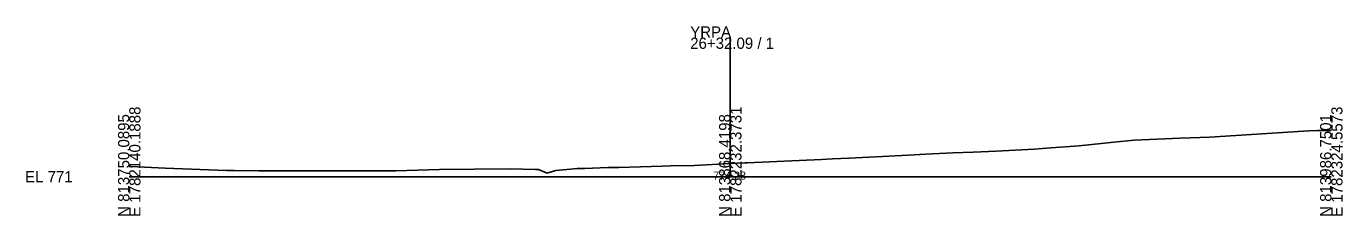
# Model space of a CAD drawing. Extents: x -26 to 2603, y -14 to 9545.
# Drawn here: x 2274.3 to 2602.8, y 3490.3 to 3537.5 of the extents above; entities that cross this region are included whole.
import ezdxf

# ---------------------------------------------------------------- set-up
doc = ezdxf.new("R2010")
doc.units = 0
for name, color, linetype in [('Exist Cross Section Cell', 7, 'Continuous'), ('Exist XS Center Line Elevation Label', 7, 'Continuous'), ('Exist XS Ground Line', 7, 'Continuous')]:
    doc.layers.add(name, color=color, linetype=linetype)

msp = doc.modelspace()

# ---------------------------------------------------------------- linework, layer by layer
at = {"layer": 'Exist Cross Section Cell'}
for p, q in [((2450, 3500), (2450, 3534.67)), ((2300, 3500), (2450, 3500)), ((2450, 3500), (2600, 3500))]:
    msp.add_line(p, q, dxfattribs=at)
at = {"layer": 'Exist XS Ground Line'}
for p, q in [((2545.71, 3508.61), (2550.78, 3509.12)), ((2550.78, 3509.12), (2562.32, 3509.64)), ((2562.32, 3509.64), (2569.71, 3509.9)), ((2569.71, 3509.9), (2593.1, 3511.32)), ((2593.1, 3511.32), (2594.45, 3511.4)), ((2594.45, 3511.4), (2596.62, 3511.52)), ((2596.62, 3511.52), (2597.5, 3511.53)), ((2597.5, 3511.53), (2600, 3511.56)), ((2494.37, 3505.38), (2498.84, 3505.63)), ((2498.84, 3505.63), (2505.53, 3505.93)), ((2505.53, 3505.93), (2510.65, 3506.15)), ((2510.65, 3506.15), (2516.37, 3506.39)), ((2516.37, 3506.39), (2525.81, 3506.83)), ((2525.81, 3506.83), (2529.97, 3507.19)), ((2529.97, 3507.19), (2537.04, 3507.71)), ((2537.04, 3507.71), (2545.71, 3508.61)), ((2300, 3502.56), (2300.36, 3502.55)), ((2300.36, 3502.55), (2308.93, 3502.1)), ((2413.71, 3502.08), (2419.42, 3502.29)), ((2419.42, 3502.29), (2422.16, 3502.33)), ((2422.16, 3502.33), (2432.99, 3502.64)), ((2432.99, 3502.64), (2435.08, 3502.69)), ((2435.08, 3502.69), (2441.06, 3502.84)), ((2441.06, 3502.84), (2450, 3503.28)), ((2450, 3503.28), (2453.6, 3503.46)), ((2453.6, 3503.46), (2454.22, 3503.49)), ((2454.22, 3503.49), (2472.73, 3504.31)), ((2472.73, 3504.31), (2475.52, 3504.45)), ((2475.52, 3504.45), (2479.68, 3504.63)), ((2479.68, 3504.63), (2487.96, 3505.03)), ((2487.96, 3505.03), (2494.37, 3505.38)), ((2308.93, 3502.1), (2324.25, 3501.58)), ((2324.25, 3501.58), (2325.11, 3501.56)), ((2325.11, 3501.56), (2325.74, 3501.56)), ((2325.74, 3501.56), (2326.21, 3501.55)), ((2326.21, 3501.55), (2332.36, 3501.5)), ((2332.36, 3501.5), (2341.54, 3501.46)), ((2341.54, 3501.46), (2342.44, 3501.44)), ((2342.44, 3501.44), (2343.86, 3501.44)), ((2343.86, 3501.44), (2366.52, 3501.51)), ((2366.52, 3501.51), (2377.45, 3501.77)), ((2377.45, 3501.77), (2386.11, 3501.92)), ((2386.11, 3501.92), (2395.28, 3501.99)), ((2395.28, 3501.99), (2401.35, 3501.79)), ((2401.35, 3501.79), (2402.13, 3501.77)), ((2402.13, 3501.77), (2404.33, 3500.91)), ((2404.33, 3500.91), (2406.1, 3501.5)), ((2406.1, 3501.5), (2406.47, 3501.56)), ((2406.47, 3501.56), (2410.15, 3501.87)), ((2410.15, 3501.87), (2411.8, 3502.05)), ((2411.8, 3502.05), (2413.71, 3502.08))]:
    msp.add_line(p, q, dxfattribs=at)

# ---------------------------------------------------------------- texts
at = {"layer": 'Exist Cross Section Cell'}
for s, p in [('YRPA', (2440, 3534.67)), ('26+32.09 / 1', (2440, 3531.87)), ('EL 771', (2274, 3498.6))]:
    msp.add_text(s, height=2.8, dxfattribs=at).set_placement(p)
for s, p in [('N 813750.0895', (2300, 3490)), ('E 1782140.1888', (2302.8, 3490)), ('N 813868.4198', (2450, 3490)), ('E 1782232.3731', (2452.8, 3490)), ('N 813986.7501', (2600, 3490)), ('E 1782324.5573', (2602.8, 3490))]:
    msp.add_text(s, height=2.8, rotation=90, dxfattribs=at).set_placement(p)
at = {"layer": 'Exist XS Center Line Elevation Label'}
msp.add_text('774.28', height=2, dxfattribs=at).set_placement((2445.73, 3499.28))

doc.saveas('drawing.dxf')
